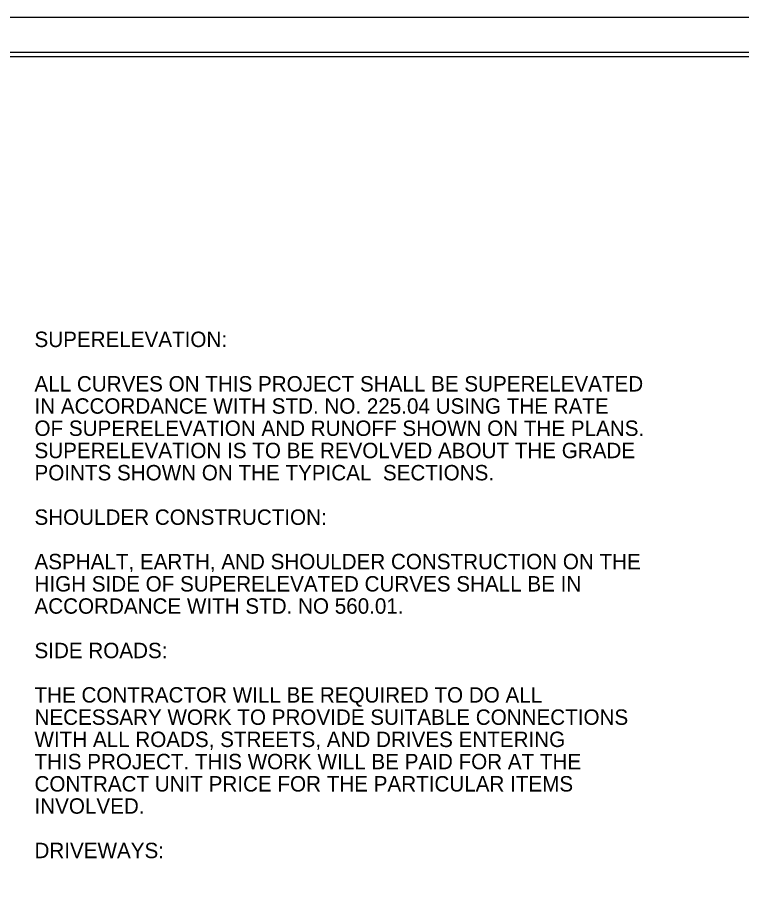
# Model space of a CAD drawing. Extents: x 2486563 to 2488026, y 371425 to 372193.
# Drawn here: x 2487122.1 to 2487286.5, y 371948.5 to 372145.1 of the extents above; entities that cross this region are included whole.
import ezdxf

# ---------------------------------------------------------------- set-up
doc = ezdxf.new("R2010")
doc.units = 0
for name, color, linetype in [('Sheet Cutting Line CELL', 7, 'Continuous'), ('Sheet Plan CELL', 7, 'Continuous'), ('Sheet Plot Border Inside CELL', 7, 'Continuous'), ('Sheet Plot Border Outside CELL', 7, 'Continuous'), ('Text', 7, 'Continuous')]:
    doc.layers.add(name, color=color, linetype=linetype)

msp = doc.modelspace()

# ---------------------------------------------------------------- linework, layer by layer
at = {"layer": 'Sheet Cutting Line CELL'}
msp.add_line((2487469.29, 372145.11), (2486795.89, 372145.11), dxfattribs=at)
at = {"layer": 'Sheet Plan CELL'}
msp.add_lwpolyline([(2487462.49, 372136.11), (2486862.49, 372136.11), (2486862.49, 371716.11), (2487462.49, 371716.11)], close=True, dxfattribs=at)
at = {"layer": 'Sheet Plot Border Inside CELL'}
msp.add_lwpolyline([(2486801.09, 371715.11), (2487467.49, 371715.11), (2487467.49, 372137.11), (2486801.09, 372137.11)], close=True, dxfattribs=at)
at = {"layer": 'Sheet Plot Border Outside CELL'}
msp.add_lwpolyline([(2486795.89, 371707.11), (2487469.29, 371707.11), (2487469.29, 372145.11), (2486795.89, 372145.11)], close=True, dxfattribs=at)

# ---------------------------------------------------------------- texts
at = {"layer": 'Text'}
for s, p in [('SUPERELEVATION:', (2487126.01, 372070.28)), ('ALL CURVES ON THIS PROJECT SHALL BE SUPERELEVATED ', (2487126.01, 372060.19)), ('IN ACCORDANCE WITH STD. NO. 225.04 USING THE RATE ', (2487126.01, 372055.15)), ('OF SUPERELEVATION AND RUNOFF SHOWN ON THE PLANS. ', (2487126.01, 372050.11)), ('SUPERELEVATION IS TO BE REVOLVED ABOUT THE GRADE ', (2487126.01, 372045.06)), ('POINTS SHOWN ON THE TYPICAL  SECTIONS.   ', (2487126.01, 372040.02)), ('SHOULDER CONSTRUCTION:', (2487126.01, 372029.93)), ('ASPHALT, EARTH, AND SHOULDER CONSTRUCTION ON THE ', (2487126.01, 372019.85)), ('HIGH SIDE OF SUPERELEVATED CURVES SHALL BE IN ', (2487126.01, 372014.8)), ('ACCORDANCE WITH STD. NO 560.01.', (2487126.01, 372009.76)), ('SIDE ROADS:', (2487126.01, 371999.67)), ('THE CONTRACTOR WILL BE REQUIRED TO DO ALL ', (2487126.01, 371989.59)), ('NECESSARY WORK TO PROVIDE SUITABLE CONNECTIONS ', (2487126.01, 371984.54)), ('WITH ALL ROADS, STREETS, AND DRIVES ENTERING ', (2487126.01, 371979.5)), ('THIS PROJECT. THIS WORK WILL BE PAID FOR AT THE ', (2487126.01, 371974.46)), ('CONTRACT UNIT PRICE FOR THE PARTICULAR ITEMS', (2487126.01, 371969.41)), ('INVOLVED.', (2487126.01, 371964.37)), ('DRIVEWAYS:', (2487126.01, 371954.28))]:
    msp.add_text(s, height=3.5, dxfattribs=at).set_placement(p)

doc.saveas('drawing.dxf')
